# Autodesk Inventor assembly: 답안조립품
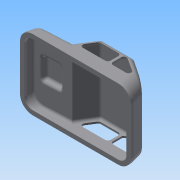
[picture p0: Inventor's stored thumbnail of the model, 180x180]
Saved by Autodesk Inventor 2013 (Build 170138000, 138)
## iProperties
Created: 2015-05
Part Number: 답안조립품
Document SubType Name: Assembly
Designer: Administrator
Author: Administrator
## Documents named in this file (2)
- C:\Documents and Settings\Administrator\바탕 화면\450508V1011\답안조립품.iam
- C:\Documents and Settings\Administrator\바탕 화면\450508V1011\1-본체.ipt
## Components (1 placed, 1 different names)
1. 1-본체:1
